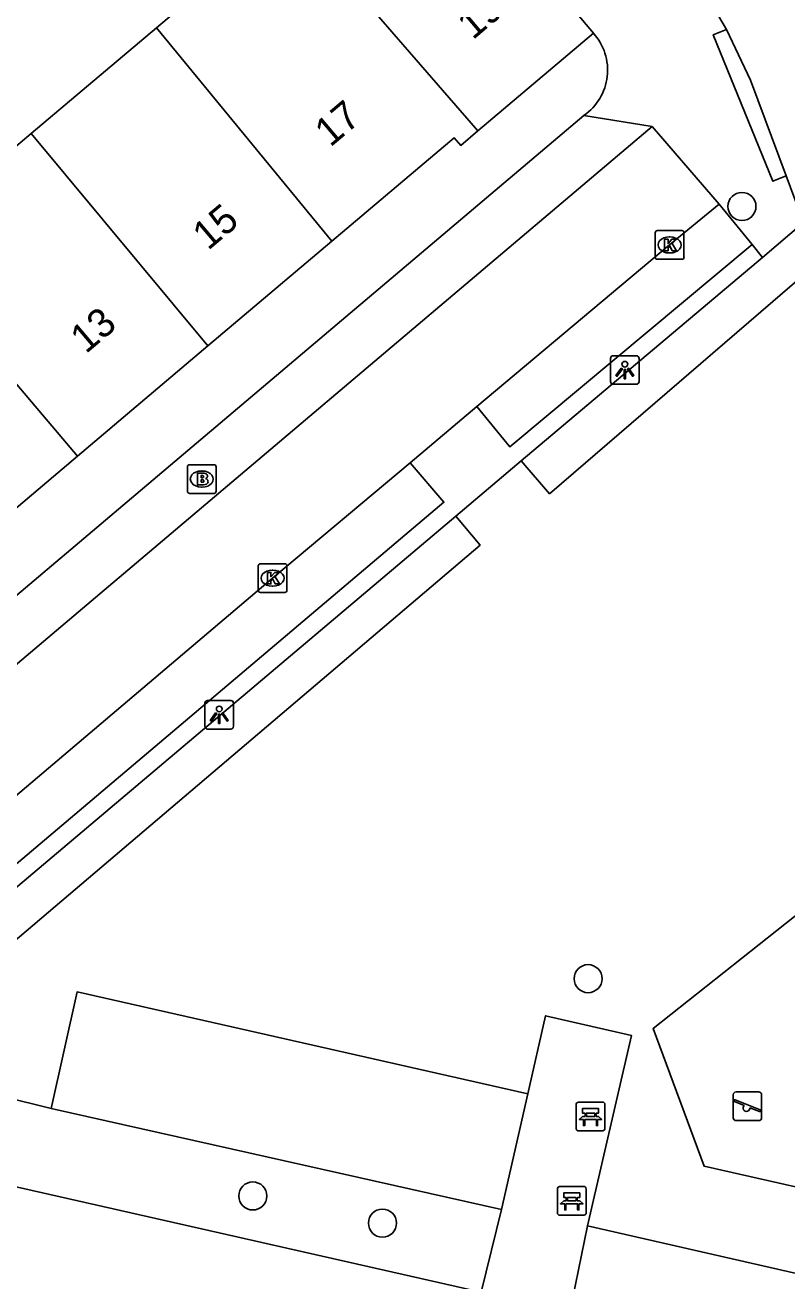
# Model space of a CAD drawing. Extents: x 162172 to 163187, y 382874 to 383684.
# Drawn here: x 162320.19 to 162346.74, y 383135.64 to 383179.43 of the extents above; entities that cross this region are included whole.
import ezdxf

# ---------------------------------------------------------------- set-up
doc = ezdxf.new("R2010")
doc.units = 0
for name, color, linetype in [('IMGEO_Bank', 7, 'Continuous'), ('IMGEO_Boom', 7, 'Continuous'), ('IMGEO_Brandkraan', 7, 'Continuous'), ('IMGEO_Groenvoorziening', 7, 'Continuous'), ('IMGEO_Haag', 7, 'Continuous'), ('IMGEO_Kolk', 7, 'Continuous'), ('IMGEO_Lichtpunt', 7, 'Continuous'), ('IMGEO_Pand', 7, 'Continuous'), ('IMGEO_Pand_nummerreeks', 7, 'Continuous'), ('IMGEO_Parkeervlak_open', 7, 'Continuous'), ('IMGEO_Rijbaan_lokaal_open', 7, 'Continuous'), ('IMGEO_Speelvoorziening', 7, 'Continuous'), ('IMGEO_Voetpad_open', 7, 'Continuous')]:
    doc.layers.add(name, color=color, linetype=linetype)

msp = doc.modelspace()

# ---------------------------------------------------------------- linework, layer by layer
at = {"layer": 'IMGEO_Bank'}
for p, q in [((162339.398, 383140.948), (162339.398, 383141.789)), ((162339.398, 383141.789), (162339.398, 383140.948)), ((162339.473, 383141.873), (162340.314, 383141.873)), ((162340.314, 383141.873), (162339.473, 383141.873)), ((162340.398, 383141.798), (162340.398, 383140.957)), ((162340.398, 383140.957), (162340.398, 383141.798)), ((162339.707, 383141.379), (162339.707, 383141.485)), ((162339.751, 383141.485), (162339.751, 383141.379)), ((162340.039, 383141.491), (162339.757, 383141.491)), ((162339.757, 383141.373), (162340.039, 383141.373)), ((162340.045, 383141.379), (162340.045, 383141.485)), ((162340.089, 383141.485), (162340.089, 383141.379)), ((162340.095, 383141.271), (162339.702, 383141.271)), ((162340.323, 383140.873), (162339.482, 383140.873)), ((162339.482, 383140.873), (162340.323, 383140.873)), ((162338.744, 383138.007), (162338.744, 383138.848)), ((162338.744, 383138.848), (162338.744, 383138.007)), ((162338.819, 383138.932), (162339.66, 383138.932)), ((162339.66, 383138.932), (162338.819, 383138.932)), ((162339.744, 383138.857), (162339.744, 383138.016)), ((162339.744, 383138.016), (162339.744, 383138.857)), ((162339.441, 383138.33), (162339.048, 383138.33)), ((162339.053, 383138.438), (162339.053, 383138.544)), ((162339.097, 383138.544), (162339.097, 383138.438)), ((162339.385, 383138.55), (162339.103, 383138.55)), ((162339.103, 383138.432), (162339.385, 383138.432)), ((162339.391, 383138.438), (162339.391, 383138.544)), ((162339.435, 383138.544), (162339.435, 383138.438)), ((162339.669, 383137.932), (162338.828, 383137.932)), ((162338.828, 383137.932), (162339.669, 383137.932))]:
    msp.add_line(p, q, dxfattribs=at)
for points in [[(162339.645, 383141.271), (162339.503, 383141.271), (162339.615, 383141.373), (162339.701, 383141.373)], [(162339.701, 383141.491), (162339.615, 383141.491), (162339.615, 383141.652), (162340.178, 383141.652), (162340.178, 383141.491), (162340.095, 383141.491)], [(162340.095, 383141.373), (162340.178, 383141.373), (162340.29, 383141.271), (162340.151, 383141.271)], [(162339.695, 383141.264), (162339.695, 383141.057), (162339.652, 383141.057), (162339.652, 383141.264)], [(162340.145, 383141.264), (162340.145, 383141.057), (162340.101, 383141.057), (162340.101, 383141.264)], [(162338.991, 383138.33), (162338.849, 383138.33), (162338.961, 383138.432), (162339.047, 383138.432)], [(162339.047, 383138.55), (162338.961, 383138.55), (162338.961, 383138.711), (162339.524, 383138.711), (162339.524, 383138.55), (162339.441, 383138.55)], [(162339.041, 383138.323), (162339.041, 383138.116), (162338.998, 383138.116), (162338.998, 383138.323)], [(162339.441, 383138.432), (162339.524, 383138.432), (162339.636, 383138.33), (162339.497, 383138.33)], [(162339.491, 383138.323), (162339.491, 383138.116), (162339.447, 383138.116), (162339.447, 383138.323)]]:
    msp.add_lwpolyline(points, dxfattribs=at)
for centre, radius, start, end in [((162339.476, 383141.795), 0.0779, 92.4484, 184.2845), ((162339.476, 383141.795), 0.0779, 92.4484, 184.2845), ((162340.32, 383141.795), 0.0779, 2.4484, 94.2845), ((162340.32, 383141.795), 0.0779, 2.4484, 94.2845), ((162339.7, 383141.484), 0.00671, 2.8957, 87.1043), ((162339.7, 383141.38), 0.00671, 272.8957, 357.1043), ((162339.757, 383141.484), 0.00671, 92.8957, 177.1043), ((162339.757, 383141.38), 0.00671, 182.8957, 267.1043), ((162340.039, 383141.484), 0.00671, 2.8957, 87.1043), ((162340.039, 383141.38), 0.00671, 272.8957, 357.1043), ((162340.096, 383141.484), 0.00671, 92.8957, 177.1043), ((162340.096, 383141.38), 0.00671, 182.8957, 267.1043), ((162339.476, 383140.951), 0.0779, 182.4484, 274.2845), ((162339.476, 383140.951), 0.0779, 182.4484, 274.2845), ((162339.645, 383141.264), 0.00671, 2.8957, 87.1043), ((162339.702, 383141.264), 0.00671, 92.8957, 177.1043), ((162340.094, 383141.264), 0.00671, 2.8957, 87.1043), ((162340.151, 383141.264), 0.00671, 92.8957, 177.1043), ((162340.32, 383140.951), 0.0779, 272.4484, 4.2845), ((162340.32, 383140.951), 0.0779, 272.4484, 4.2845), ((162338.822, 383138.854), 0.0779, 92.4484, 184.2845), ((162338.822, 383138.854), 0.0779, 92.4484, 184.2845), ((162339.666, 383138.854), 0.0779, 2.4484, 94.2845), ((162339.666, 383138.854), 0.0779, 2.4484, 94.2845), ((162338.991, 383138.323), 0.00671, 2.8957, 87.1043), ((162339.048, 383138.323), 0.00671, 92.8957, 177.1043), ((162339.046, 383138.543), 0.00671, 2.8957, 87.1043), ((162339.046, 383138.439), 0.00671, 272.8957, 357.1043), ((162339.103, 383138.543), 0.00671, 92.8957, 177.1043), ((162339.103, 383138.439), 0.00671, 182.8957, 267.1043), ((162339.385, 383138.543), 0.00671, 2.8957, 87.1043), ((162339.385, 383138.439), 0.00671, 272.8957, 357.1043), ((162339.442, 383138.543), 0.00671, 92.8957, 177.1043), ((162339.442, 383138.439), 0.00671, 182.8957, 267.1043), ((162339.44, 383138.323), 0.00671, 2.8957, 87.1043), ((162339.497, 383138.323), 0.00671, 92.8957, 177.1043), ((162338.822, 383138.01), 0.0779, 182.4484, 274.2845), ((162338.822, 383138.01), 0.0779, 182.4484, 274.2845), ((162339.666, 383138.01), 0.0779, 272.4484, 4.2845), ((162339.666, 383138.01), 0.0779, 272.4484, 4.2845)]:
    msp.add_arc(centre, radius, start, end, dxfattribs=at)
at = {"layer": 'IMGEO_Boom'}
for centre in [(162345.175, 383173.105), (162339.814, 383146.179), (162328.126, 383138.603), (162332.644, 383137.656)]:
    msp.add_circle(centre, 0.489, dxfattribs=at)
at = {"layer": 'IMGEO_Brandkraan'}
for p, q in [((162325.847, 383163.174), (162325.847, 383164.026)), ((162325.922, 383164.1), (162326.774, 383164.1)), ((162326.335, 383163.88), (162326.36, 383163.88)), ((162326.848, 383164.026), (162326.848, 383163.174)), ((162326.358, 383163.32), (162326.333, 383163.32)), ((162326.774, 383163.1), (162325.922, 383163.1))]:
    msp.add_line(p, q, dxfattribs=at)
for points in [[(162325.847, 383163.174), (162325.847, 383164.026)], [(162325.922, 383164.1), (162326.774, 383164.1)], [(162326.195, 383163.8), (162326.195, 383163.4), (162326.408, 383163.4)], [(162326.426, 383163.8), (162326.195, 383163.8)], [(162326.374, 383163.719), (162326.32, 383163.719), (162326.32, 383163.643)], [(162326.848, 383164.026), (162326.848, 383163.174)], [(162326.32, 383163.643), (162326.373, 383163.643)], [(162326.382, 383163.567), (162326.32, 383163.567), (162326.32, 383163.486)], [(162326.32, 383163.486), (162326.382, 383163.486)], [(162326.774, 383163.1), (162325.922, 383163.1)]]:
    msp.add_lwpolyline(points, dxfattribs=at)
for centre, radius, start, end in [((162325.924, 383164.024), 0.0765, 91.552, 178.448), ((162325.924, 383164.024), 0.0765, 91.552, 178.448), ((162326.375, 383163.681), 0.0379, 267.8285, 90.9355), ((162326.43, 383163.655), 0.145, 59.4692, 91.5367), ((162326.455, 383163.702), 0.0922, 285.5137, 58.1501), ((162326.772, 383164.024), 0.0765, 1.552, 88.448), ((162326.772, 383164.024), 0.0765, 1.552, 88.448), ((162326.383, 383163.526), 0.0404, 269.8759, 90.5077), ((162326.414, 383163.651), 0.251, 268.6676, 293.5347), ((162326.46, 383163.51), 0.105, 301.3115, 78.989), ((162325.924, 383163.176), 0.0765, 181.552, 268.448), ((162325.924, 383163.176), 0.0765, 181.552, 268.448), ((162326.772, 383163.176), 0.0765, 271.552, 358.448), ((162326.772, 383163.176), 0.0765, 271.552, 358.448)]:
    msp.add_arc(centre, radius, start, end, dxfattribs=at)
for centre, major_axis, ratio, start_param, end_param in [((162326.334, 383163.6), (-0.387, 0.002), 0.722429, 4.712389, 7.853982), ((162326.359, 383163.6), (-0.39, 0.002), 0.717154, 1.570796, 4.712389)]:
    msp.add_ellipse(centre, major_axis=major_axis, ratio=ratio, start_param=start_param, end_param=end_param, dxfattribs=at)
at = {"layer": 'IMGEO_Groenvoorziening'}
for points in [[(162350.087, 383150.79), (162342.077, 383144.444), (162343.858, 383139.638), (162353.661, 383137.425), (162354.761, 383138.409), (162350.087, 383150.79)], [(162337.716, 383142.168), (162322, 383145.717), (162321.096, 383141.652)], [(162321.096, 383141.652), (162314.53, 383143.278)], [(162321.096, 383141.652), (162336.798, 383138.127)], [(162358.231, 383133.358), (162339.793, 383137.559)]]:
    msp.add_lwpolyline(points, dxfattribs=at)
at = {"layer": 'IMGEO_Haag'}
for points in [[(162337.483, 383164.232), (162338.468, 383163.089), (162347.838, 383171.163)], [(162335.202, 383162.307), (162336.048, 383161.296), (162319.29, 383147.041), (162318.422, 383148.141)]]:
    msp.add_lwpolyline(points, dxfattribs=at)
at = {"layer": 'IMGEO_Kolk'}
for p, q in [((162342.154, 383171.335), (162342.154, 383172.187)), ((162342.229, 383172.261), (162343.081, 383172.261)), ((162342.642, 383172.041), (162342.667, 383172.041)), ((162343.155, 383172.187), (162343.155, 383171.335)), ((162343.081, 383171.261), (162342.229, 383171.261)), ((162342.665, 383171.481), (162342.64, 383171.481)), ((162328.39, 383160.645), (162329.242, 383160.645)), ((162328.315, 383159.719), (162328.315, 383160.571)), ((162328.803, 383160.425), (162328.828, 383160.425)), ((162329.316, 383160.571), (162329.316, 383159.719)), ((162328.826, 383159.865), (162328.801, 383159.865)), ((162329.242, 383159.645), (162328.39, 383159.645))]:
    msp.add_line(p, q, dxfattribs=at)
for points in [[(162342.154, 383171.335), (162342.154, 383172.187)], [(162342.229, 383172.261), (162343.081, 383172.261)], [(162343.155, 383172.187), (162343.155, 383171.335)], [(162342.475, 383171.961), (162342.598, 383171.961), (162342.598, 383171.81), (162342.728, 383171.961), (162342.892, 383171.961), (162342.746, 383171.81), (162342.899, 383171.561), (162342.747, 383171.561), (162342.662, 383171.725), (162342.598, 383171.658), (162342.598, 383171.561), (162342.475, 383171.561), (162342.475, 383171.961)], [(162343.081, 383171.261), (162342.229, 383171.261)], [(162328.39, 383160.645), (162329.242, 383160.645)], [(162328.315, 383159.719), (162328.315, 383160.571)], [(162328.636, 383160.345), (162328.759, 383160.345), (162328.759, 383160.194), (162328.889, 383160.345), (162329.053, 383160.345), (162328.907, 383160.194), (162329.06, 383159.945), (162328.908, 383159.945), (162328.823, 383160.109), (162328.759, 383160.042), (162328.759, 383159.945), (162328.636, 383159.945), (162328.636, 383160.345)], [(162329.316, 383160.571), (162329.316, 383159.719)], [(162329.242, 383159.645), (162328.39, 383159.645)]]:
    msp.add_lwpolyline(points, dxfattribs=at)
for centre, start, end in [((162342.231, 383172.185), 91.552, 178.448), ((162342.231, 383172.185), 91.552, 178.448), ((162343.079, 383172.185), 1.552, 88.448), ((162343.079, 383172.185), 1.552, 88.448), ((162342.231, 383171.337), 181.552, 268.448), ((162342.231, 383171.337), 181.552, 268.448), ((162343.079, 383171.337), 271.552, 358.448), ((162343.079, 383171.337), 271.552, 358.448), ((162328.392, 383160.569), 91.552, 178.448), ((162328.392, 383160.569), 91.552, 178.448), ((162329.24, 383160.569), 1.552, 88.448), ((162329.24, 383160.569), 1.552, 88.448), ((162328.392, 383159.721), 181.552, 268.448), ((162328.392, 383159.721), 181.552, 268.448), ((162329.24, 383159.721), 271.552, 358.448), ((162329.24, 383159.721), 271.552, 358.448)]:
    msp.add_arc(centre, 0.0765, start, end, dxfattribs=at)
for centre, major_axis, ratio, start_param, end_param in [((162342.641, 383171.761), (-0.387, 0.002), 0.722429, 4.712389, 7.853982), ((162342.666, 383171.761), (-0.39, 0.002), 0.717154, 1.570796, 4.712389), ((162328.802, 383160.145), (-0.387, 0.002), 0.722429, 4.712389, 7.853982), ((162328.827, 383160.145), (-0.39, 0.002), 0.717154, 1.570796, 4.712389)]:
    msp.add_ellipse(centre, major_axis=major_axis, ratio=ratio, start_param=start_param, end_param=end_param, dxfattribs=at)
at = {"layer": 'IMGEO_Lichtpunt'}
for p, q in [((162340.594, 383167.805), (162340.594, 383166.998)), ((162340.594, 383167.805), (162340.594, 383166.998)), ((162341.496, 383167.9), (162340.688, 383167.9)), ((162341.496, 383167.9), (162340.688, 383167.9)), ((162341.59, 383166.998), (162341.59, 383167.805)), ((162341.59, 383166.998), (162341.59, 383167.805)), ((162340.688, 383166.904), (162341.496, 383166.904)), ((162340.688, 383166.904), (162341.496, 383166.904)), ((162327.358, 383155.88), (162326.55, 383155.88)), ((162327.358, 383155.88), (162326.55, 383155.88)), ((162326.456, 383155.785), (162326.456, 383154.978)), ((162326.456, 383155.785), (162326.456, 383154.978)), ((162327.452, 383154.978), (162327.452, 383155.785)), ((162327.452, 383154.978), (162327.452, 383155.785)), ((162326.55, 383154.884), (162327.358, 383154.884)), ((162326.55, 383154.884), (162327.358, 383154.884))]:
    msp.add_line(p, q, dxfattribs=at)
for points in [[(162340.968, 383167.469), (162341.007, 383167.441), (162340.819, 383167.179), (162340.781, 383167.206), (162340.968, 383167.469)], [(162341.07, 383167.421), (162341.117, 383167.421), (162341.117, 383167.099), (162341.07, 383167.099), (162341.07, 383167.421)], [(162341.18, 383167.441), (162341.218, 383167.468), (162341.405, 383167.206), (162341.366, 383167.178), (162341.18, 383167.441)], [(162326.83, 383155.449), (162326.869, 383155.421), (162326.681, 383155.159), (162326.643, 383155.186), (162326.83, 383155.449)], [(162326.932, 383155.401), (162326.979, 383155.401), (162326.979, 383155.079), (162326.932, 383155.079), (162326.932, 383155.401)], [(162327.042, 383155.421), (162327.08, 383155.448), (162327.267, 383155.186), (162327.228, 383155.158), (162327.042, 383155.421)]]:
    msp.add_lwpolyline(points, dxfattribs=at)
for centre in [(162341.093, 383167.603), (162326.955, 383155.583)]:
    msp.add_circle(centre, 0.0994, dxfattribs=at)
for centre, start, end in [((162340.688, 383167.805), 90, 180), ((162340.688, 383167.805), 90, 180), ((162341.496, 383167.805), 0, 90), ((162341.496, 383167.805), 0, 90), ((162340.688, 383166.998), 180, 270), ((162340.688, 383166.998), 180, 270), ((162341.496, 383166.998), 270, 0), ((162341.496, 383166.998), 270, 360), ((162326.55, 383155.785), 90, 180), ((162326.55, 383155.785), 90, 180), ((162327.358, 383155.785), 0, 90), ((162327.358, 383155.785), 0, 90), ((162326.55, 383154.978), 180, 270), ((162326.55, 383154.978), 180, 270), ((162327.358, 383154.978), 270, 0), ((162327.358, 383154.978), 270, 360)]:
    msp.add_arc(centre, 0.0946, start, end, dxfattribs=at)
at = {"layer": 'IMGEO_Pand'}
for points in [[(162333.317, 383187.038), (162336.823, 383182.913), (162339.995, 383179.146)], [(162329.205, 383183.544), (162328.7, 383183.115), (162328.927, 383182.849), (162324.77, 383179.335)], [(162329.205, 383183.544), (162335.969, 383175.736)], [(162324.77, 383179.335), (162320.403, 383175.643)], [(162330.88, 383171.894), (162324.77, 383179.335)], [(162335.969, 383175.736), (162339.995, 383179.146)], [(162320.403, 383175.643), (162315.788, 383171.741)], [(162326.561, 383168.244), (162320.403, 383175.643)], [(162335.969, 383175.736), (162335.373, 383175.231), (162335.143, 383175.498), (162330.88, 383171.894)], [(162315.788, 383171.741), (162322.016, 383164.402)], [(162326.561, 383168.244), (162330.88, 383171.894)], [(162322.016, 383164.402), (162326.561, 383168.244)], [(162322.016, 383164.402), (162317.811, 383160.846)]]:
    msp.add_lwpolyline(points, dxfattribs=at)
at = {"layer": 'IMGEO_Parkeervlak_open'}
msp.add_lwpolyline([(162336.083, 383135.244), (162312.528, 383140.586)], dxfattribs=at)
at = {"layer": 'IMGEO_Rijbaan_lokaal_open'}
for points in [[(162344.636, 383179.27), (162344.215, 383179.988), (162343.809, 383180.374)], [(162346.713, 383174.171), (162345.477, 383177.503), (162344.636, 383179.27)], [(162303.781, 383143.539), (162304.504, 383144.126), (162342.05, 383175.889)], [(162342.05, 383175.889), (162344.383, 383173.184)], [(162347.325, 383172.541), (162346.713, 383174.171)], [(162335.935, 383166.133), (162342.654, 383171.762), (162344.383, 383173.184)], [(162335.935, 383166.133), (162333.613, 383164.164)], [(162316.419, 383149.634), (162319.473, 383152.215), (162328.815, 383160.146), (162333.613, 383164.164)]]:
    msp.add_lwpolyline(points, dxfattribs=at)
at = {"layer": 'IMGEO_Speelvoorziening'}
for p, q in [((162344.969, 383142.231), (162345.759, 383142.231)), ((162345.759, 383142.231), (162344.969, 383142.231)), ((162344.869, 383141.331), (162344.869, 383142.131)), ((162344.869, 383142.131), (162344.869, 383141.331)), ((162345.252, 383141.759), (162344.913, 383141.896)), ((162344.938, 383141.956), (162345.814, 383141.603)), ((162345.859, 383142.131), (162345.859, 383141.331)), ((162345.859, 383141.331), (162345.859, 383142.131)), ((162345.79, 383141.543), (162345.45, 383141.68)), ((162345.759, 383141.231), (162344.969, 383141.231)), ((162344.969, 383141.231), (162345.759, 383141.231))]:
    msp.add_line(p, q, dxfattribs=at)
for centre, radius, start, end in [((162344.969, 383142.131), 0.1, 90, 180), ((162344.969, 383142.131), 0.1, 90, 180), ((162345.759, 383142.131), 0.1, 0, 90), ((162345.759, 383142.131), 0.1, 360, 90), ((162344.926, 383141.926), 0.0327, 68.078, 248.078), ((162345.331, 383141.669), 0.12, 130.9928, 5.1632), ((162345.802, 383141.573), 0.0327, 248.078, 68.078), ((162344.969, 383141.331), 0.1, 180, 270), ((162344.969, 383141.331), 0.1, 180, 270), ((162345.759, 383141.331), 0.1, 270, 0), ((162345.759, 383141.331), 0.1, 270, 0)]:
    msp.add_arc(centre, radius, start, end, dxfattribs=at)
at = {"layer": 'IMGEO_Voetpad_open'}
for points in [[(162346.713, 383174.171), (162346.25, 383173.983), (162344.173, 383179.082), (162344.636, 383179.27)], [(162339.665, 383176.277), (162303.372, 383145.574)], [(162339.665, 383176.277), (162342.05, 383175.889)], [(162344.383, 383173.184), (162345.536, 383171.775)], [(162345.888, 383171.328), (162347.325, 383172.541)], [(162345.536, 383171.775), (162337.082, 383164.723), (162335.935, 383166.133)], [(162345.536, 383171.775), (162345.888, 383171.328)], [(162345.888, 383171.328), (162337.483, 383164.232)], [(162333.613, 383164.164), (162334.784, 383162.792), (162317.605, 383148.249), (162316.419, 383149.634)], [(162335.202, 383162.307), (162337.483, 383164.232)], [(162318.422, 383148.141), (162335.202, 383162.307)], [(162339.793, 383137.559), (162341.329, 383144.192), (162338.332, 383144.886), (162337.716, 383142.168)], [(162337.716, 383142.168), (162336.798, 383138.127)], [(162336.798, 383138.127), (162336.083, 383135.244)], [(162339.165, 383134.493), (162339.793, 383137.559)]]:
    msp.add_lwpolyline(points, dxfattribs=at)
msp.add_arc((162338.572, 383177.856), 1.921, 304.6881, 42.189, dxfattribs=at)

# ---------------------------------------------------------------- texts
at = {"layer": 'IMGEO_Pand_nummerreeks'}
for s, rotation, p in [('19', 40.2644, (162335.793, 383178.889)), ('17', 40.2091, (162330.825, 383175.147)), ('15', 40.2091, (162326.565, 383171.546)), ('13', 40.2091, (162322.305, 383167.945))]:
    msp.add_text(s, height=1, rotation=rotation, dxfattribs=at).set_placement(p)

doc.saveas('drawing.dxf')
